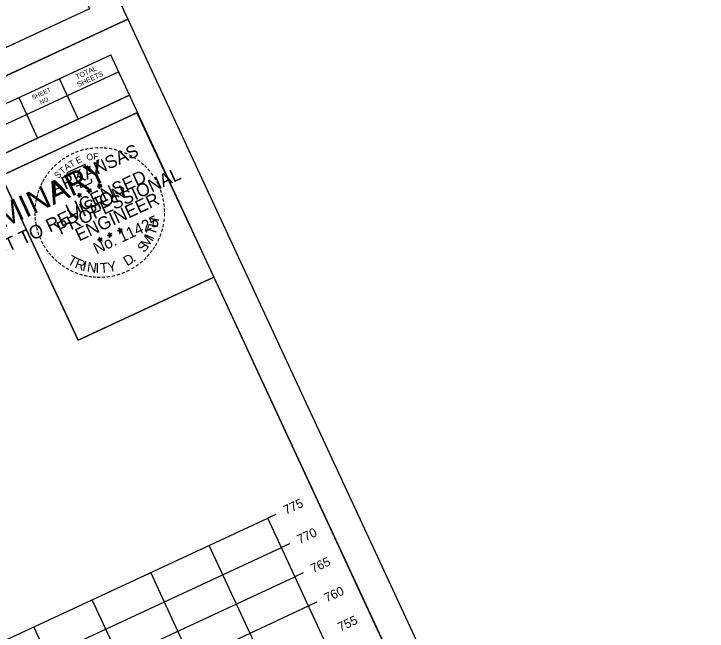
# Model space of a CAD drawing. Extents: x 1354696 to 1366163, y 660729 to 670380.
# Drawn here: x 1358197.6 to 1358305.1, y 666168.5 to 666264.3 of the extents above; entities that cross this region are included whole.
import ezdxf

# ---------------------------------------------------------------- set-up
doc = ezdxf.new("R2010")
doc.units = 0
for name, color, linetype in [('R_Axis', 7, 'Continuous'), ('R_Axis Annot', 7, 'Continuous'), ('R_Border', 7, 'Continuous'), ('R_Border PE', 7, 'Continuous'), ('R_Border Prem', 7, 'Continuous'), ('R_Grid', 7, 'Continuous'), ('R_No Plot', 7, 'Continuous')]:
    doc.layers.add(name, color=color, linetype=linetype)

msp = doc.modelspace()

# ---------------------------------------------------------------- linework, layer by layer
at = {"layer": 'R_Axis'}
for p, q in [((1358238.22, 666186.61), (1358236.95, 666186.02)), ((1358255.9, 666145.21), (1358236.95, 666186.02)), ((1358240.32, 666182.08), (1358239.06, 666181.49)), ((1358242.43, 666177.54), (1358241.16, 666176.95)), ((1358244.54, 666173.01), (1358243.27, 666172.42))]:
    msp.add_line(p, q, dxfattribs=at)
at = {"layer": 'R_Border'}
for p, q in [((1358209.28, 666265.06), (1357922.5, 666131.91)), ((1357925.81, 666124.77), (1358212.59, 666257.91)), ((1358299.11, 666071.56), (1358212.59, 666257.91)), ((1358213.83, 666255.25), (1358174.74, 666237.1)), ((1358213.82, 666255.26), (1358213.82, 666255.26)), ((1358204.61, 666254.21), (1358207.53, 666247.91)), ((1358215.51, 666251.62), (1358176.42, 666233.47)), ((1358179.11, 666234.72), (1358215.51, 666251.62)), ((1358198.32, 666251.28), (1358201.24, 666244.99)), ((1358216.75, 666248.95), (1358159.94, 666222.57))]:
    msp.add_line(p, q, dxfattribs=at)
at = {"layer": 'R_Border PE'}
for p, q in [((1358209.27, 666236.82), (1358209.12, 666237.15)), ((1358209.12, 666237.15), (1358209.27, 666236.94)), ((1358209.12, 666237.15), (1358209.19, 666236.9)), ((1358209.54, 666237.06), (1358209.27, 666236.82)), ((1358209.54, 666237.06), (1358209.3, 666236.9)), ((1358209.54, 666237.06), (1358209.4, 666236.89)), ((1358210.51, 666237.5), (1358210.76, 666237.57)), ((1358210.51, 666237.5), (1358210.88, 666237.55)), ((1358210.51, 666237.5), (1358210.78, 666237.49)), ((1358210.88, 666237.55), (1358210.72, 666237.88)), ((1358210.72, 666237.88), (1358210.87, 666237.67)), ((1358210.72, 666237.88), (1358210.79, 666237.63)), ((1358210.81, 666237.19), (1358210.88, 666237.55)), ((1358210.81, 666237.19), (1358210.91, 666237.48)), ((1358210.81, 666237.19), (1358210.82, 666237.46)), ((1358211.14, 666237.8), (1358210.88, 666237.55)), ((1358211.19, 666237.37), (1358210.88, 666237.55)), ((1358211.14, 666237.8), (1358210.91, 666237.63)), ((1358211.19, 666237.37), (1358210.91, 666237.47)), ((1358211.19, 666237.37), (1358210.95, 666237.58)), ((1358211.14, 666237.8), (1358211, 666237.62)), ((1358207.39, 666236.07), (1358207.64, 666236.13)), ((1358207.39, 666236.07), (1358207.76, 666236.11)), ((1358207.39, 666236.07), (1358207.66, 666236.06)), ((1358207.76, 666236.11), (1358207.6, 666236.44)), ((1358207.6, 666236.44), (1358207.75, 666236.24)), ((1358207.6, 666236.44), (1358207.67, 666236.2)), ((1358207.69, 666235.75), (1358207.76, 666236.11)), ((1358207.69, 666235.75), (1358207.79, 666236.04)), ((1358207.69, 666235.75), (1358207.7, 666236.03)), ((1358208.02, 666236.36), (1358207.76, 666236.11)), ((1358208.07, 666235.93), (1358207.76, 666236.11)), ((1358208.02, 666236.36), (1358207.79, 666236.2)), ((1358208.07, 666235.93), (1358207.79, 666236.04)), ((1358208.07, 666235.93), (1358207.83, 666236.14)), ((1358208.02, 666236.36), (1358207.88, 666236.18)), ((1358208.91, 666236.77), (1358209.16, 666236.84)), ((1358208.91, 666236.77), (1358209.27, 666236.82)), ((1358208.91, 666236.77), (1358209.17, 666236.76)), ((1358209.2, 666236.46), (1358209.27, 666236.82)), ((1358209.2, 666236.46), (1358209.3, 666236.74)), ((1358209.2, 666236.46), (1358209.21, 666236.73)), ((1358209.59, 666236.64), (1358209.27, 666236.82)), ((1358209.59, 666236.64), (1358209.3, 666236.74)), ((1358209.59, 666236.64), (1358209.34, 666236.84)), ((1358213.7, 666230.63), (1358213.95, 666230.7)), ((1358213.7, 666230.63), (1358214.06, 666230.68)), ((1358213.7, 666230.63), (1358213.97, 666230.62)), ((1358214.06, 666230.68), (1358213.91, 666231.01)), ((1358213.91, 666231.01), (1358214.06, 666230.81)), ((1358213.91, 666231.01), (1358213.98, 666230.77)), ((1358213.99, 666230.32), (1358214.06, 666230.68)), ((1358213.99, 666230.32), (1358214.09, 666230.61)), ((1358213.99, 666230.32), (1358214, 666230.59)), ((1358214.33, 666230.93), (1358214.06, 666230.68)), ((1358214.38, 666230.5), (1358214.06, 666230.68)), ((1358214.33, 666230.93), (1358214.09, 666230.76)), ((1358214.38, 666230.5), (1358214.1, 666230.6)), ((1358214.38, 666230.5), (1358214.13, 666230.71)), ((1358214.33, 666230.93), (1358214.19, 666230.75)), ((1358210.94, 666229.24), (1358210.79, 666229.57)), ((1358210.79, 666229.57), (1358210.94, 666229.37)), ((1358210.79, 666229.57), (1358210.86, 666229.33)), ((1358211.21, 666229.49), (1358210.94, 666229.24)), ((1358211.21, 666229.49), (1358210.97, 666229.32)), ((1358211.21, 666229.49), (1358211.07, 666229.31)), ((1358212.09, 666229.9), (1358212.34, 666229.97)), ((1358212.09, 666229.9), (1358212.46, 666229.95)), ((1358212.09, 666229.9), (1358212.36, 666229.89)), ((1358212.46, 666229.95), (1358212.3, 666230.28)), ((1358212.3, 666230.28), (1358212.45, 666230.07)), ((1358212.3, 666230.28), (1358212.37, 666230.03)), ((1358212.38, 666229.59), (1358212.46, 666229.95)), ((1358212.38, 666229.59), (1358212.49, 666229.87)), ((1358212.38, 666229.59), (1358212.4, 666229.86)), ((1358212.72, 666230.19), (1358212.46, 666229.95)), ((1358212.77, 666229.77), (1358212.46, 666229.95)), ((1358212.72, 666230.19), (1358212.48, 666230.03)), ((1358212.77, 666229.77), (1358212.49, 666229.87)), ((1358212.77, 666229.77), (1358212.53, 666229.97)), ((1358212.72, 666230.19), (1358212.58, 666230.01)), ((1358210.58, 666229.2), (1358210.83, 666229.26)), ((1358210.58, 666229.2), (1358210.94, 666229.24)), ((1358210.58, 666229.2), (1358210.84, 666229.19)), ((1358210.87, 666228.88), (1358210.94, 666229.24)), ((1358210.87, 666228.88), (1358210.97, 666229.17)), ((1358210.87, 666228.88), (1358210.88, 666229.16)), ((1358211.26, 666229.06), (1358210.94, 666229.24)), ((1358211.26, 666229.06), (1358210.97, 666229.17)), ((1358211.26, 666229.06), (1358211.01, 666229.27))]:
    msp.add_line(p, q, dxfattribs=at)
for points in [[(1358209.37, 666240.24), (1358209.38, 666240.56), (1358208.77, 666240.25), (1358208.62, 666240.91), (1358205.8, 666239.6)], [(1358205.8, 666239.6), (1358206.39, 666238.96)], [(1358207.26, 666237.61), (1358207.3, 666237.53), (1358207.82, 666237.75), (1358207.97, 666237.3), (1358209.67, 666238.09), (1358209.62, 666238.66)], [(1358209.12, 666237.15), (1358209.59, 666236.64), (1358208.91, 666236.77), (1358209.54, 666237.06), (1358209.2, 666236.46), (1358209.12, 666237.15)], [(1358210.72, 666237.88), (1358211.19, 666237.37), (1358210.51, 666237.5), (1358211.14, 666237.8), (1358210.81, 666237.19), (1358210.72, 666237.88)], [(1358207.6, 666236.44), (1358208.07, 666235.93), (1358207.39, 666236.07), (1358208.02, 666236.36), (1358207.69, 666235.75), (1358207.6, 666236.44)], [(1358213.91, 666231.01), (1358214.38, 666230.5), (1358213.7, 666230.63), (1358214.33, 666230.93), (1358213.99, 666230.32), (1358213.91, 666231.01)], [(1358210.79, 666229.57), (1358211.26, 666229.06), (1358210.58, 666229.2), (1358211.21, 666229.49), (1358210.87, 666228.88), (1358210.79, 666229.57)], [(1358212.3, 666230.28), (1358212.77, 666229.77), (1358212.09, 666229.9), (1358212.72, 666230.19), (1358212.38, 666229.59), (1358212.3, 666230.28)]]:
    msp.add_lwpolyline(points, dxfattribs=at)
for centre, radius in [((1358209.27, 666236.82), 0.172), ((1358209.27, 666236.82), 0.145), ((1358210.88, 666237.55), 0.172), ((1358210.88, 666237.55), 0.145), ((1358210.88, 666237.55), 0.116), ((1358210.88, 666237.55), 0.0991), ((1358210.88, 666237.55), 0.0747), ((1358210.88, 666237.55), 0.0495), ((1358210.88, 666237.55), 0.0296), ((1358207.76, 666236.11), 0.172), ((1358207.76, 666236.11), 0.145), ((1358207.76, 666236.11), 0.116), ((1358207.76, 666236.11), 0.0991), ((1358207.76, 666236.11), 0.0747), ((1358207.76, 666236.11), 0.0495), ((1358207.76, 666236.11), 0.0296), ((1358209.27, 666236.82), 0.116), ((1358209.27, 666236.82), 0.0991), ((1358209.27, 666236.82), 0.0747), ((1358209.27, 666236.82), 0.0495), ((1358209.27, 666236.82), 0.0296), ((1358214.06, 666230.68), 0.172), ((1358214.06, 666230.68), 0.145), ((1358214.06, 666230.68), 0.116), ((1358214.06, 666230.68), 0.0991), ((1358214.06, 666230.68), 0.0747), ((1358214.06, 666230.68), 0.0495), ((1358214.06, 666230.68), 0.0296), ((1358210.94, 666229.24), 0.172), ((1358212.46, 666229.94), 0.172), ((1358212.46, 666229.94), 0.145), ((1358212.46, 666229.94), 0.116), ((1358212.46, 666229.94), 0.0991), ((1358212.46, 666229.94), 0.0747), ((1358212.46, 666229.94), 0.0495), ((1358212.46, 666229.94), 0.0296), ((1358210.94, 666229.24), 0.145), ((1358210.94, 666229.24), 0.116), ((1358210.94, 666229.24), 0.0991), ((1358210.94, 666229.24), 0.0747), ((1358210.94, 666229.24), 0.0495), ((1358210.94, 666229.24), 0.0296)]:
    msp.add_circle(centre, radius, dxfattribs=at)
at = {"layer": 'R_Grid'}
for p, q in [((1357964.85, 666059.69), (1358236.95, 666186.02)), ((1358255.9, 666145.21), (1358236.95, 666186.02)), ((1357966.95, 666055.16), (1358239.06, 666181.49)), ((1358246.83, 666141), (1358227.88, 666181.81)), ((1357969.06, 666050.62), (1358241.16, 666176.95)), ((1358237.76, 666136.79), (1358218.81, 666177.6)), ((1357971.16, 666046.09), (1358243.27, 666172.42)), ((1358228.69, 666132.58), (1358209.74, 666173.39)), ((1358219.62, 666128.37), (1358200.67, 666169.18))]:
    msp.add_line(p, q, dxfattribs=at)
at = {"layer": 'R_No Plot'}
for p, q in [((1357912.92, 666123.08), (1358215.26, 666263.45)), ((1357912.93, 666123.08), (1358215.26, 666263.45)), ((1358204.47, 666218.49), (1358204.47, 666218.49))]:
    msp.add_line(p, q, dxfattribs=at)
for points in [[(1357823.08, 666316.58), (1358125.43, 666456.95), (1358215.26, 666263.45), (1357912.92, 666123.08)], [(1358048.14, 666416.77), (1358065.94, 666425.04), (1358070.1, 666416.07), (1358084.71, 666422.86), (1358105.76, 666432.63), (1358117.72, 666407.14), (1358138.77, 666416.91), (1358209.28, 666265.06), (1357922.5, 666131.91), (1357835.98, 666318.27)], [(1357912.92, 666123.08), (1358215.26, 666263.45), (1358305.1, 666069.95), (1358002.76, 665929.58)], [(1358195.59, 666239.13), (1358216.64, 666248.9), (1358228.61, 666223.41), (1358207.56, 666213.64)], [(1358137.98, 666223.27), (1358155.78, 666231.53), (1358159.94, 666222.57), (1358174.55, 666229.36), (1358195.59, 666239.13), (1358207.56, 666213.64), (1358228.61, 666223.41), (1358299.11, 666071.56), (1358012.33, 665938.41), (1357925.81, 666124.77)]]:
    msp.add_lwpolyline(points, close=True, dxfattribs=at)

# ---------------------------------------------------------------- texts
at = {"layer": 'R_Axis Annot'}
for s, p in [('775', (1358239.78, 666186.57)), ('770', (1358241.89, 666182.03)), ('765', (1358243.99, 666177.5)), ('760', (1358246.1, 666172.96)), ('755', (1358248.21, 666168.43))]:
    msp.add_text(s, height=1.4, rotation=24.9042, dxfattribs=at).set_placement(p)
at = {"layer": 'R_Border'}
for s, height, p in [('TOTAL', 0.782, (1358207.36, 666254.07)), ('SHEETS', 0.782, (1358207.61, 666252.89)), ('SHEET', 0.684, (1358200.54, 666250.91)), ('NO.', 0.684, (1358201.75, 666250.17))]:
    msp.add_text(s, height=height, rotation=24.9042, dxfattribs=at).set_placement(p)
at = {"layer": 'R_Border PE'}
for s, height, rotation, p in [('ARKANSAS', 2, 24.9042, (1358203.91, 666236.2)), ('-', 1.6, 12.1091, (1358208.66, 666242.62)), ('-', 1.6, 7.2404, (1358209.3, 666242.74)), ('-', 1.6, 2.7593, (1358210.06, 666242.85)), ('-', 1.6, 359.0253, (1358210.75, 666242.87)), ('-', 1.6, 354.5451, (1358211.39, 666242.86)), ('-', 1.6, 350.7668, (1358212.12, 666242.8)), ('-', 1.6, 30.801, (1358205.93, 666241.47)), ('-', 1.6, 25.0904, (1358206.6, 666241.86)), ('-', 1.6, 22.6472, (1358207.26, 666242.15)), ('-', 1.6, 17.0659, (1358207.96, 666242.42)), ('O', 1, 15.3557, (1358208.97, 666241.44)), ('F', 1, 4.9748, (1358209.93, 666241.63)), ('-', 1.6, 345.4339, (1358212.86, 666242.67)), ('-', 1.6, 340.4828, (1358213.61, 666242.48)), ('-', 1.6, 334.7839, (1358214.35, 666242.22)), ('-', 1.6, 331.5563, (1358215.08, 666241.9)), ('-', 1.6, 38.5343, (1358204.77, 666240.63)), ('-', 1.6, 35.1235, (1358205.31, 666241.06)), ('T', 1, 30.9269, (1358206.47, 666240.39)), ('E', 1, 25.7365, (1358207.43, 666240.95)), ('-', 1.4, 328.5795, (1358215.76, 666241.59)), ('-', 1.6, 324.5725, (1358216.31, 666241.17)), ('-', 1.6, 49.2114, (1358203.73, 666239.59)), ('-', 1.6, 44.0802, (1358204.19, 666240.1)), ('T', 1, 41.3078, (1358205.13, 666239.3)), ('A', 1, 36.1173, (1358205.77, 666239.88)), ('-', 1.6, 319.567, (1358216.86, 666240.75)), ('-', 1.6, 315.477, (1358217.34, 666240.34)), ('-', 1.6, 310.0274, (1358217.79, 666239.91)), ('-', 1.6, 58.9677, (1358202.9, 666238.44)), ('-', 1.6, 53.696, (1358203.28, 666239.03)), ('S', 1, 46.4982, (1358204.44, 666238.62)), ('PROFESSIONAL', 2, 24.9042, (1358204.8, 666229.94)), ('LICENSED', 2, 24.9042, (1358206.2, 666232.69)), ('-', 1.6, 305.4535, (1358218.29, 666239.32)), ('-', 1.6, 63.8548, (1358202.27, 666237.3)), ('-', 1.6, 61.1359, (1358202.54, 666237.84)), ('-', 1.6, 301.5003, (1358218.76, 666238.69)), ('-', 1.6, 299.2343, (1358219.12, 666238.06)), ('-', 1.6, 67.8664, (1358202.05, 666236.74)), ('DWB', 0.01, 24.9042, (1358210.87, 666237.54)), ('-', 1.6, 294.8448, (1358219.41, 666237.5)), ('-', 1.6, 288.4214, (1358219.68, 666236.89)), ('-', 1.6, 75.5183, (1358201.69, 666235.51)), ('-', 1.6, 73.3272, (1358201.85, 666236.12)), ('ENGINEER', 2, 24.9042, (1358207.68, 666228.94)), ('DWB', 0.01, 24.9042, (1358207.75, 666236.1)), ('DWB', 0.01, 24.9042, (1358209.26, 666236.81)), ('-', 1.6, 285.8995, (1358219.89, 666236.27)), ('-', 1.6, 82.9748, (1358201.48, 666234.2)), ('-', 1.6, 79.1366, (1358201.55, 666234.82)), ('-', 1.6, 280.6668, (1358220.07, 666235.61)), ('-', 1.6, 277.7723, (1358220.21, 666234.88)), ('-', 1.6, 87.7755, (1358201.45, 666233.51)), ('-', 1.6, 272.7928, (1358220.29, 666234.17)), ('-', 1.6, 92.6784, (1358201.47, 666232.85)), ('-', 1.6, 97.2986, (1358201.54, 666232.19)), ('No. 11425', 1.757, 24.9042, (1358210.4, 666226.94)), ('-', 1.6, 269.5239, (1358220.32, 666233.49)), ('-', 1.6, 100.3651, (1358201.66, 666231.46)), ('H', 1.54, 79.513, (1358219.89, 666231.05)), ('-', 1.6, 258.7494, (1358220.19, 666231.88)), ('-', 1.6, 263.9754, (1358220.28, 666232.64)), ('-', 1.6, 106.1054, (1358201.84, 666230.75)), ('-', 1.6, 110.0905, (1358202.06, 666230.1)), ('DWB', 0.01, 24.9042, (1358214.05, 666230.67)), ('T', 1.54, 71.5486, (1358219.48, 666229.82)), ('-', 1.6, 256.1579, (1358220.04, 666231.19)), ('-', 1.6, 113.9664, (1358202.34, 666229.45)), ('DWB', 0.01, 24.9042, (1358212.45, 666229.94)), ('M', 1.54, 57.5605, (1358218.37, 666227.84)), ('I', 1.54, 67.0178, (1358219.17, 666229.15)), ('-', 1.6, 245.9893, (1358219.58, 666229.79)), ('-', 1.6, 250.6695, (1358219.84, 666230.47)), ('-', 1.6, 119.1, (1358202.67, 666228.81)), ('-', 1.6, 123.8521, (1358203.02, 666228.23)), ('DWB', 0.01, 24.9042, (1358210.93, 666229.23)), ('S', 1.54, 51.8354, (1358217.78, 666227.12)), ('-', 1.6, 240.6405, (1358219.28, 666229.13)), ('-', 1.6, 126.6191, (1358203.45, 666227.62)), ('-', 1.6, 130.362, (1358203.85, 666227.15)), ('-', 1.6, 232.261, (1358218.6, 666228.01)), ('-', 1.6, 237.1533, (1358218.96, 666228.56)), ('-', 1.6, 133.9916, (1358204.31, 666226.67)), ('-', 1.6, 138.9685, (1358204.79, 666226.24)), ('T', 1.54, 330.9447, (1358205.77, 666225.56)), ('R', 1.54, 338.9091, (1358206.9, 666224.93)), ('D', 1.54, 31.3011, (1358215.14, 666225.09)), ('-', 1.6, 225.6226, (1358217.72, 666226.95)), ('-', 1.6, 229.1558, (1358218.17, 666227.46)), ('-', 1.6, 140.633, (1358205.33, 666225.81)), ('-', 1.6, 145.3513, (1358205.9, 666225.42)), ('I', 1.54, 346.8735, (1358208.11, 666224.47)), ('N', 1.54, 351.4044, (1358208.83, 666224.28)), ('I', 1.54, 0.2645, (1358210.25, 666224.07)), ('T', 1.54, 4.7953, (1358210.99, 666224.05)), ('Y', 1.54, 12.7597, (1358212.28, 666224.16)), ('.', 1.54, 38.6683, (1358216.17, 666225.71)), ('-', 1.6, 216.1899, (1358216.63, 666225.96)), ('-', 1.6, 220.3785, (1358217.21, 666226.44)), ('-', 1.6, 150.7976, (1358206.5, 666225.09)), ('-', 1.6, 155.6223, (1358207.15, 666224.78)), ('-', 1.6, 159.128, (1358207.85, 666224.5)), ('-', 1.6, 201.4224, (1358214.65, 666224.79)), ('-', 1.6, 206.4959, (1358215.32, 666225.12)), ('-', 1.6, 210.7208, (1358216.02, 666225.53)), ('-', 1.6, 163.838, (1358208.52, 666224.3)), ('-', 1.6, 169.5505, (1358209.2, 666224.17)), ('-', 1.6, 172.9939, (1358209.86, 666224.07)), ('-', 1.6, 176.4746, (1358210.52, 666224.02)), ('-', 1.6, 179.5044, (1358211.1, 666224.01)), ('-', 1.6, 183.4654, (1358211.77, 666224.05)), ('-', 1.6, 187.7024, (1358212.49, 666224.14)), ('-', 1.6, 192.4597, (1358213.21, 666224.29)), ('-', 1.6, 198.0196, (1358213.95, 666224.52))]:
    msp.add_text(s, height=height, rotation=rotation, dxfattribs=at).set_placement(p)
at = {"layer": 'R_Border Prem'}
for s, height, p in [('PRELIMINARY', 3.5, (1358183.6, 666225.25)), ('SUBJECT TO REVISION', 2.0751, (1358186.77, 666222.72))]:
    msp.add_text(s, height=height, rotation=24.9042, dxfattribs=at).set_placement(p)

doc.saveas('drawing.dxf')
